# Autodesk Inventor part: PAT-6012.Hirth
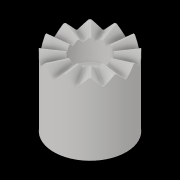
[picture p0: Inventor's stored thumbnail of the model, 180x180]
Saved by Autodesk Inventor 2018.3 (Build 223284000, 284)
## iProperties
Created: 2020-03
Part Number: PAT-6012.Hirth
Material: Generic
Document SubType Name: Modeling
Designer: Th. Mörgeli
Mass: 17.6441 g
Surface Area: 48.3626 cm^2
Volume: 17.6441 cm^3
Density: 1 g/cm^3
Appearance: Default
Author: Th. Mörgeli
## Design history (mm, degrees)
sketch "Sketch2"
  geometry: L1 (-7, 2.028)-(-7, -8); L2 (-7, -8)-(-6, -9); L3 (-6, -9)-(-6, -15); L4 (-6, -15)-(0, -17.184); L5 (0, -17.184)-(0, -28); L6 (0, -28)-(-15, -28); L7 (-15, -28)-(-15, 2.028); L8 (-15, 2.028)-(-7, 2.028); 1 further point
  constraints: 16 end point, 2 parallel, 2 perpendicular, 1 horizontal, 1 point on line, 1 vertical
  dimensions: "d8" = 14 diameter of L1 L5 (= Gewindebohrungsdurchmesser); "d10" = 12 diameter of L3 L5 (= Bohrungsdurchmesser); "d11" = 8 vertical distance of L1.end point (0, 0) (= Gewindetiefe); "d12" = 15 vertical distance of L3.end point (0, 0) (= Bohrungstiefe); "d14" = 45 deg angle of L1 L2; "d15" = 70 deg angle of L5 L4; "d16" = 2.02793 distance from line of point (0, 0) L8 (= 0.5 x Zahnhoehe); "d17" = 30 diameter of L7 L5 (= Aussendurchmesser); "d18" = 28 distance from line of point (0, 0) L6 (= Laenge)
revolve "Grundkoerper" sketch "Sketch2" stored, may be unused: angle "d19" = 90 deg
sketch "SKIZZE Ebene"
  geometry: L1 (0, 0)-(-15, 0); L2 (-15, 0)-(-15, -2.028); L3 (-15, -2.028)-(0, 0); L4 (-15, -2.028)-(-15.274, 0); 1 further point
  constraints: 8 end point, 2 perpendicular, 1 coincident, 1 horizontal, 1 point on line
  dimensions: "d20" = 15 distance of L1.start L1.end (= 0.5 x Aussendurchmesser); "d21" = 7.69944 deg angle of L1 L3 (= Neigungswinkel)
node "EBENE"
sketch "Sketch4"
  geometry: L1 (0, 0)-(8.112, 8.112); L2 (8.112, 8.112)-(8.112, -8.112); L3 (8.112, -8.112)-(0, 0); L4 (0, 0)-(8.112, 0)
  constraints: 8 end point, 1 midpoint, 1 perpendicular, 1 vertical, 1 other
  dimensions: "d23" = 90 deg angle of L1 L3 (= Flankenwinkel); "d24" = 8.11172 distance of L1.start L4.end (= 2 x Zahnhoehe)
extrude "Zahnluecke" cut sketch "Sketch4" extent not by distance; stored distance "d25" = 10; taper "d26" = 0 deg
fillet "Fillet1" dims "d27" = 0.5 (= Fussradius)
pattern_circular "Circular Pattern1" dims angle "d29" = 360 deg
chamfer "Chamfer1" distance "d31" = 0.49497 (= 0.707107 x Kopfflaeche); stored, may be unused: second distance "d32" = 2, angle "d33" = 45 deg
body "Solid2"
other parameters: "Aussendurchmesser" = 30 [user parameter; used in 3 equation terms], "Laenge" = 28 [user parameter; used in 1 equation term], "Gewindebohrungsdurchmesser" = 14 [user parameter; used in 1 equation term], "Gewindetiefe" = 8 [user parameter; used in 1 equation term], "Bohrungsdurchmesser" = 12 [user parameter; used in 1 equation term], "Bohrungstiefe" = 15 [user parameter; used in 1 equation term], "Zahnhoehe" = 4.05586 (computed from Aussendurchmesser, Neigungswinkel) [user parameter; used in 2 equation terms], "Neigungswinkel" = 7.69944 deg [user parameter; used in 2 equation terms], "d22" = 90 deg, "Flankenwinkel" = 90 deg [user parameter; used in 1 equation term], "Fussradius" = 0.5 [user parameter; used in 1 equation term], "Kopfflaeche" = 0.7 [user parameter; used in 1 equation term]
